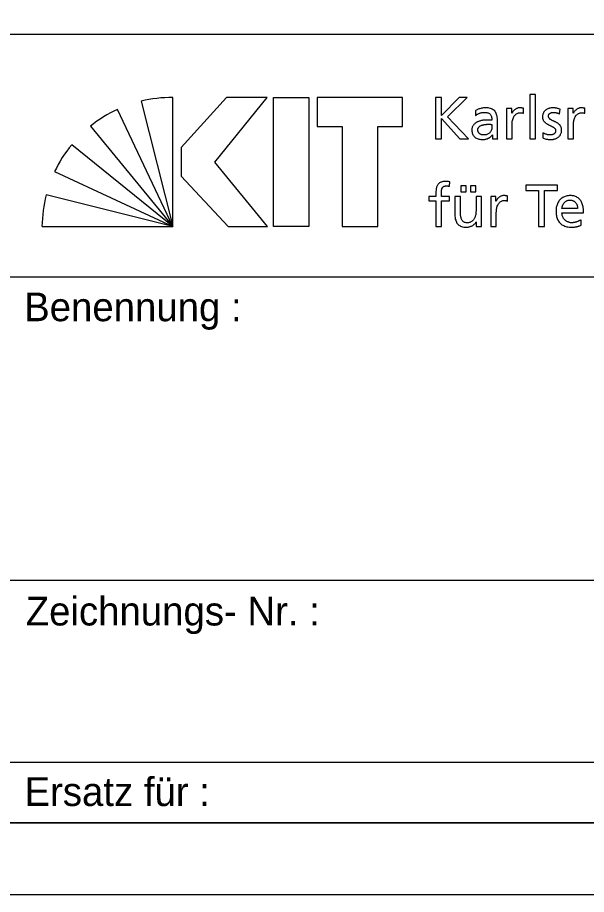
# Model space of a CAD drawing. Extents: x 0 to 119, y 0 to 84.
# Drawn here: x 101.13 to 109.07, y 0 to 12.23 of the extents above; entities that cross this region are included whole.
import ezdxf

# ---------------------------------------------------------------- set-up
doc = ezdxf.new("R2010")
doc.units = 0
doc.layers.add('90_Plankopf', color=7, linetype='Continuous')

msp = doc.modelspace()

# ---------------------------------------------------------------- linework, layer by layer
at = {"layer": '90_Plankopf'}
for p, q in [((82.224, 11.998), (117.8, 11.998)), ((82.224, 11.998), (117.8, 11.998)), ((102.855, 11.067), (103.296, 9.317)), ((103.296, 9.317), (103.296, 11.117)), ((106.962, 11.117), (106.962, 10.541)), ((103.296, 9.317), (102.527, 10.95)), ((107.516, 10.932), (107.52, 10.866)), ((108.185, 10.897), (108.185, 10.966)), ((108.691, 10.888), (108.698, 10.956)), ((109.042, 10.897), (109.042, 10.966)), ((107.824, 10.624), (107.824, 10.798)), ((102.149, 10.717), (103.296, 9.317)), ((107.746, 10.742), (107.746, 10.705)), ((106.962, 10.541), (107.044, 10.541)), ((107.301, 10.541), (107.422, 10.541)), ((108.459, 10.624), (108.455, 10.554)), ((103.296, 9.317), (101.887, 10.457)), ((101.648, 10.083), (103.296, 9.317)), ((107.155, 9.879), (107.158, 9.941)), ((103.296, 9.317), (101.532, 9.758)), ((107.965, 9.673), (107.965, 9.742)), ((108.941, 9.568), (108.723, 9.568)), ((108.723, 9.51), (109.024, 9.51)), ((101.473, 9.317), (103.296, 9.317)), ((108.992, 9.335), (108.992, 9.412)), ((101, 8.614), (117.8, 8.614)), ((101, 4.384), (117.8, 4.384)), ((101, 1.846), (117.8, 1.846)), ((117.8, 1), (82.224, 1)), ((84.56, 1), (117.8, 1)), ((84.56, 1), (117.8, 1))]:
    msp.add_line(p, q, dxfattribs=at)
for points in [[(0, 0), (118.8, 0), (118.8, 84), (0, 84)], [(5, 83), (117.8, 83), (117.8, 1), (5, 1)], [(104.613, 11.117), (104.047, 11.117), (103.415, 10.42), (103.415, 10.018), (104.068, 9.317), (104.617, 9.317), (103.884, 10.213)], [(105.194, 11.117), (105.194, 9.317), (104.7, 9.317), (104.7, 11.117)], [(105.312, 11.117), (105.312, 10.712), (105.66, 10.712), (105.66, 9.317), (106.154, 9.317), (106.154, 10.712), (106.502, 10.712), (106.502, 11.117)]]:
    msp.add_lwpolyline(points, close=True, dxfattribs=at)
for points in [[(108.276, 10.541), (108.354, 10.541), (108.354, 11.16), (108.276, 11.16), (108.276, 10.541)], [(107.422, 10.541), (107.129, 10.845), (107.4, 11.117), (107.29, 11.117), (107.044, 10.864), (107.044, 11.117), (106.962, 11.117)], [(108.024, 10.897), (108.023, 10.897), (108.023, 10.962), (107.95, 10.962), (107.95, 10.541), (108.028, 10.541), (108.028, 10.733)], [(108.881, 10.897), (108.88, 10.897), (108.88, 10.962), (108.807, 10.962), (108.807, 10.541), (108.885, 10.541), (108.885, 10.733)], [(107.044, 10.541), (107.044, 10.823), (107.301, 10.541)], [(107.753, 10.596), (107.754, 10.596), (107.754, 10.541), (107.827, 10.541)], [(107.311, 9.885), (107.311, 9.803), (107.388, 9.803), (107.388, 9.885), (107.311, 9.885)], [(107.446, 9.885), (107.446, 9.803), (107.524, 9.803), (107.524, 9.885), (107.446, 9.885)], [(108.398, 9.317), (108.481, 9.317), (108.481, 9.821), (108.66, 9.821), (108.66, 9.893), (108.219, 9.893), (108.219, 9.821), (108.398, 9.821), (108.398, 9.317)], [(106.965, 9.777), (106.965, 9.738), (106.866, 9.738), (106.866, 9.676), (106.965, 9.676), (106.965, 9.317), (107.042, 9.317), (107.042, 9.676), (107.154, 9.676), (107.154, 9.738), (107.042, 9.738), (107.042, 9.784)], [(107.308, 9.52), (107.308, 9.738), (107.231, 9.738), (107.231, 9.488)], [(107.603, 9.317), (107.603, 9.738), (107.525, 9.738), (107.525, 9.543)], [(107.804, 9.673), (107.803, 9.673), (107.803, 9.738), (107.73, 9.738), (107.73, 9.317), (107.808, 9.317), (107.808, 9.509)], [(107.526, 9.384), (107.528, 9.384), (107.528, 9.317), (107.603, 9.317)]]:
    msp.add_lwpolyline(points, dxfattribs=at)
for centre, start, end in [((103.29, 9.211), 89.8053, 103.1895), ((103.332, 9.224), 115.0126, 128.3968), ((103.363, 9.253), 140.7898, 154.174), ((103.378, 9.288), 165.7222, 179.1064)]:
    msp.add_arc(centre, 1.906, start, end, dxfattribs=at)
for points in [[(107.824, 10.798), (107.824, 10.836), (107.818, 10.868), (107.807, 10.894), (107.795, 10.92), (107.777, 10.939), (107.752, 10.952), (107.727, 10.965), (107.694, 10.972), (107.654, 10.972), (107.628, 10.972), (107.603, 10.968), (107.58, 10.961), (107.556, 10.954), (107.535, 10.944), (107.516, 10.932)], [(107.52, 10.866), (107.531, 10.875), (107.543, 10.883), (107.556, 10.889), (107.569, 10.896), (107.583, 10.901), (107.598, 10.904), (107.613, 10.908), (107.627, 10.909), (107.642, 10.909), (107.668, 10.909), (107.688, 10.905), (107.704, 10.897), (107.719, 10.889), (107.73, 10.877), (107.736, 10.86), (107.743, 10.844), (107.746, 10.824), (107.746, 10.799)], [(108.185, 10.966), (108.18, 10.967), (108.175, 10.968), (108.17, 10.969), (108.165, 10.97), (108.16, 10.971), (108.154, 10.971), (108.148, 10.972), (108.142, 10.972), (108.134, 10.972), (108.119, 10.972), (108.105, 10.969), (108.09, 10.962), (108.076, 10.956), (108.064, 10.947), (108.052, 10.936), (108.041, 10.925), (108.031, 10.912), (108.024, 10.897)], [(108.028, 10.733), (108.028, 10.768), (108.033, 10.799), (108.042, 10.824), (108.051, 10.85), (108.065, 10.87), (108.082, 10.883), (108.099, 10.897), (108.119, 10.904), (108.142, 10.904), (108.149, 10.904), (108.156, 10.904), (108.164, 10.903), (108.171, 10.902), (108.178, 10.9), (108.185, 10.897)], [(108.698, 10.956), (108.683, 10.96), (108.667, 10.964), (108.652, 10.967), (108.636, 10.97), (108.619, 10.972), (108.601, 10.972), (108.581, 10.972), (108.561, 10.969), (108.543, 10.964), (108.525, 10.959), (108.509, 10.951), (108.496, 10.94), (108.482, 10.929), (108.472, 10.916), (108.464, 10.9), (108.457, 10.883), (108.453, 10.864), (108.453, 10.842), (108.453, 10.826), (108.456, 10.811), (108.463, 10.799), (108.469, 10.787), (108.478, 10.776), (108.489, 10.767), (108.5, 10.758), (108.512, 10.75), (108.525, 10.743), (108.538, 10.736), (108.551, 10.729), (108.563, 10.723), (108.576, 10.717), (108.588, 10.711), (108.599, 10.704), (108.61, 10.698), (108.619, 10.691), (108.625, 10.683), (108.632, 10.675), (108.635, 10.665), (108.635, 10.654), (108.635, 10.643), (108.633, 10.633), (108.628, 10.626), (108.623, 10.618), (108.617, 10.612), (108.609, 10.607), (108.601, 10.602), (108.593, 10.599), (108.583, 10.597), (108.574, 10.595), (108.565, 10.594), (108.556, 10.594), (108.548, 10.594), (108.539, 10.595), (108.528, 10.597), (108.517, 10.599), (108.505, 10.603), (108.493, 10.607), (108.481, 10.612), (108.47, 10.617), (108.459, 10.624)], [(108.455, 10.554), (108.473, 10.545), (108.492, 10.539), (108.512, 10.536), (108.531, 10.532), (108.551, 10.531), (108.571, 10.531), (108.59, 10.531), (108.608, 10.534), (108.625, 10.539), (108.643, 10.544), (108.659, 10.552), (108.673, 10.563), (108.686, 10.574), (108.697, 10.588), (108.705, 10.604), (108.714, 10.621), (108.718, 10.64), (108.718, 10.662), (108.718, 10.682), (108.714, 10.698), (108.708, 10.711), (108.701, 10.724), (108.692, 10.736), (108.682, 10.745), (108.671, 10.754), (108.659, 10.762), (108.646, 10.769), (108.633, 10.776), (108.62, 10.782), (108.607, 10.787), (108.594, 10.793), (108.582, 10.799), (108.572, 10.805), (108.561, 10.812), (108.552, 10.819), (108.545, 10.827), (108.539, 10.836), (108.536, 10.846), (108.535, 10.858), (108.536, 10.87), (108.539, 10.879), (108.546, 10.887), (108.553, 10.894), (108.562, 10.9), (108.573, 10.904), (108.584, 10.908), (108.596, 10.909), (108.61, 10.909), (108.614, 10.909), (108.62, 10.909), (108.628, 10.908), (108.635, 10.906), (108.643, 10.905), (108.651, 10.903), (108.659, 10.901), (108.667, 10.898), (108.674, 10.896), (108.681, 10.893), (108.687, 10.891), (108.691, 10.888)], [(109.042, 10.966), (109.037, 10.967), (109.032, 10.968), (109.027, 10.969), (109.022, 10.97), (109.017, 10.971), (109.011, 10.971), (109.005, 10.972), (108.999, 10.972), (108.991, 10.972), (108.976, 10.972), (108.962, 10.969), (108.947, 10.962), (108.933, 10.956), (108.921, 10.947), (108.909, 10.936), (108.898, 10.925), (108.888, 10.912), (108.881, 10.897)], [(108.885, 10.733), (108.885, 10.768), (108.89, 10.799), (108.899, 10.824), (108.908, 10.85), (108.922, 10.87), (108.939, 10.883), (108.956, 10.897), (108.976, 10.904), (108.999, 10.904), (109.006, 10.904), (109.013, 10.904), (109.021, 10.903), (109.028, 10.902), (109.035, 10.9), (109.042, 10.897)], [(107.746, 10.799), (107.736, 10.8), (107.727, 10.8), (107.718, 10.801), (107.709, 10.801), (107.7, 10.801), (107.692, 10.801), (107.683, 10.801), (107.674, 10.801), (107.664, 10.801), (107.647, 10.801), (107.63, 10.8), (107.613, 10.797), (107.595, 10.794), (107.577, 10.789), (107.56, 10.783), (107.543, 10.776), (107.528, 10.768), (107.514, 10.757), (107.5, 10.746), (107.489, 10.733), (107.481, 10.718), (107.472, 10.702), (107.468, 10.684), (107.468, 10.662), (107.468, 10.632), (107.475, 10.607), (107.488, 10.588), (107.501, 10.568), (107.519, 10.554), (107.542, 10.545), (107.565, 10.536), (107.592, 10.531), (107.622, 10.531), (107.64, 10.531), (107.656, 10.534), (107.67, 10.538), (107.684, 10.542), (107.697, 10.547), (107.707, 10.554), (107.718, 10.56), (107.727, 10.567), (107.735, 10.575), (107.742, 10.582), (107.748, 10.589), (107.753, 10.596)], [(107.746, 10.705), (107.746, 10.684), (107.742, 10.665), (107.733, 10.648), (107.724, 10.631), (107.711, 10.618), (107.693, 10.609), (107.676, 10.599), (107.654, 10.594), (107.629, 10.594), (107.62, 10.594), (107.611, 10.596), (107.602, 10.598), (107.593, 10.601), (107.584, 10.606), (107.576, 10.611), (107.569, 10.617), (107.562, 10.625), (107.558, 10.633), (107.553, 10.641), (107.551, 10.651), (107.55, 10.662), (107.551, 10.677), (107.554, 10.69), (107.562, 10.699), (107.569, 10.709), (107.578, 10.717), (107.59, 10.723), (107.601, 10.729), (107.614, 10.733), (107.627, 10.736), (107.64, 10.739), (107.653, 10.741), (107.665, 10.742), (107.677, 10.743), (107.688, 10.743), (107.697, 10.743), (107.705, 10.743), (107.713, 10.743), (107.721, 10.743), (107.73, 10.742), (107.738, 10.742), (107.746, 10.742)], [(107.827, 10.541), (107.826, 10.545), (107.826, 10.551), (107.825, 10.557), (107.825, 10.564), (107.824, 10.573), (107.824, 10.584), (107.824, 10.595), (107.824, 10.608), (107.824, 10.624)], [(107.158, 9.941), (107.15, 9.942), (107.142, 9.944), (107.134, 9.945), (107.125, 9.946), (107.116, 9.946), (107.106, 9.946), (107.078, 9.946), (107.054, 9.942), (107.036, 9.934), (107.017, 9.926), (107.003, 9.915), (106.992, 9.9), (106.982, 9.885), (106.975, 9.867), (106.971, 9.847), (106.967, 9.826), (106.965, 9.803), (106.965, 9.777)], [(107.042, 9.784), (107.042, 9.798), (107.043, 9.811), (107.045, 9.823), (107.046, 9.835), (107.05, 9.846), (107.055, 9.855), (107.06, 9.864), (107.068, 9.871), (107.078, 9.876), (107.088, 9.881), (107.101, 9.883), (107.118, 9.883), (107.124, 9.883), (107.131, 9.883), (107.138, 9.882), (107.144, 9.881), (107.15, 9.88), (107.155, 9.879)], [(107.965, 9.742), (107.96, 9.743), (107.955, 9.744), (107.95, 9.745), (107.945, 9.746), (107.94, 9.747), (107.934, 9.747), (107.928, 9.748), (107.922, 9.748), (107.914, 9.748), (107.899, 9.748), (107.885, 9.745), (107.87, 9.738), (107.856, 9.732), (107.844, 9.723), (107.832, 9.712), (107.821, 9.701), (107.811, 9.688), (107.804, 9.673)], [(107.808, 9.509), (107.808, 9.544), (107.813, 9.575), (107.822, 9.6), (107.832, 9.626), (107.845, 9.646), (107.862, 9.659), (107.879, 9.673), (107.899, 9.68), (107.922, 9.68), (107.929, 9.681), (107.936, 9.68), (107.944, 9.679), (107.951, 9.678), (107.958, 9.676), (107.965, 9.673)], [(109.024, 9.51), (109.024, 9.544), (109.021, 9.576), (109.014, 9.605), (109.008, 9.634), (108.998, 9.659), (108.984, 9.68), (108.969, 9.701), (108.95, 9.718), (108.926, 9.73), (108.902, 9.742), (108.873, 9.748), (108.838, 9.748), (108.808, 9.748), (108.781, 9.743), (108.757, 9.732), (108.733, 9.722), (108.712, 9.707), (108.695, 9.688), (108.677, 9.669), (108.664, 9.647), (108.655, 9.621), (108.646, 9.595), (108.641, 9.567), (108.641, 9.535), (108.641, 9.501), (108.645, 9.47), (108.654, 9.442), (108.662, 9.414), (108.676, 9.39), (108.694, 9.37), (108.712, 9.35), (108.734, 9.334), (108.762, 9.324), (108.789, 9.313), (108.821, 9.308), (108.859, 9.307), (108.882, 9.308), (108.901, 9.309), (108.917, 9.312), (108.933, 9.315), (108.947, 9.319), (108.959, 9.323), (108.971, 9.327), (108.982, 9.331), (108.992, 9.335)], [(108.723, 9.568), (108.725, 9.582), (108.728, 9.596), (108.733, 9.609), (108.738, 9.623), (108.744, 9.636), (108.754, 9.647), (108.762, 9.659), (108.774, 9.668), (108.787, 9.675), (108.801, 9.682), (108.817, 9.685), (108.836, 9.685), (108.853, 9.685), (108.868, 9.682), (108.881, 9.676), (108.894, 9.67), (108.905, 9.662), (108.914, 9.651), (108.923, 9.64), (108.93, 9.628), (108.934, 9.614), (108.939, 9.6), (108.941, 9.584), (108.941, 9.568)], [(107.525, 9.543), (107.525, 9.518), (107.523, 9.494), (107.518, 9.473), (107.513, 9.452), (107.505, 9.434), (107.495, 9.418), (107.484, 9.403), (107.471, 9.391), (107.455, 9.383), (107.439, 9.374), (107.419, 9.37), (107.397, 9.37), (107.375, 9.371), (107.357, 9.378), (107.344, 9.389), (107.331, 9.4), (107.322, 9.417), (107.316, 9.439), (107.311, 9.46), (107.308, 9.488), (107.308, 9.52)], [(107.231, 9.488), (107.231, 9.45), (107.236, 9.418), (107.247, 9.391), (107.259, 9.364), (107.276, 9.343), (107.299, 9.329), (107.322, 9.315), (107.352, 9.308), (107.388, 9.307), (107.408, 9.308), (107.427, 9.311), (107.445, 9.317), (107.463, 9.323), (107.479, 9.332), (107.493, 9.343), (107.507, 9.354), (107.518, 9.368), (107.526, 9.384)], [(108.992, 9.412), (108.987, 9.408), (108.98, 9.404), (108.97, 9.399), (108.961, 9.394), (108.951, 9.39), (108.939, 9.385), (108.927, 9.381), (108.914, 9.377), (108.901, 9.374), (108.888, 9.372), (108.875, 9.37), (108.862, 9.37), (108.843, 9.37), (108.826, 9.374), (108.809, 9.38), (108.793, 9.387), (108.778, 9.397), (108.765, 9.409), (108.752, 9.421), (108.742, 9.436), (108.735, 9.453), (108.727, 9.471), (108.723, 9.49), (108.723, 9.51)]]:
    msp.add_open_spline(points, degree=3, dxfattribs=at)

# ---------------------------------------------------------------- texts
for s, p in [('Benennung :', (101.223, 7.996)), ('Zeichnungs- Nr. :', (101.245, 3.752)), ('Ersatz für :', (101.228, 1.234))]:
    msp.add_text(s, height=0.4, dxfattribs=at).set_placement(p)

doc.saveas('drawing.dxf')
